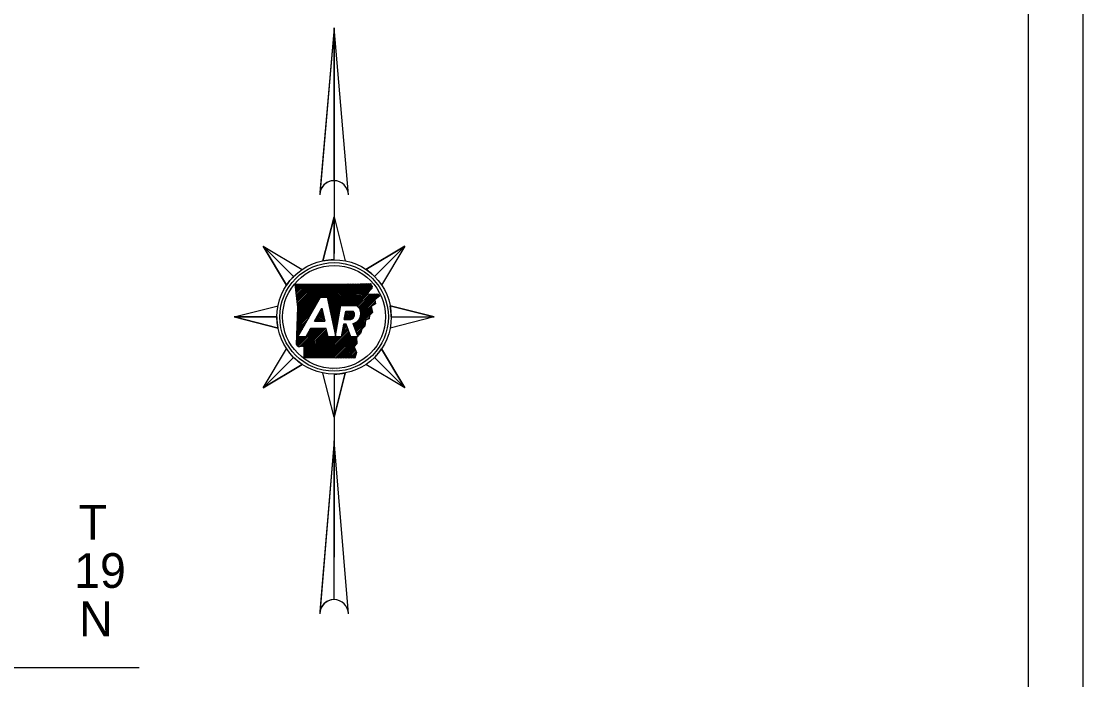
# Model space of a CAD drawing. Extents: x 19118 to 454486, y 1325406 to 1693506.
# Drawn here: x 26165 to 27093, y 1325966 to 1326542 of the extents above; entities that cross this region are included whole.
import ezdxf

# ---------------------------------------------------------------- set-up
doc = ezdxf.new("R2010")
doc.units = 0
for name, color, linetype in [('S_CURB', 7, 'Continuous'), ('S_EDGE_PAVEMENT', 7, 'Continuous'), ('S_MSC_PT_SYM', 7, 'Continuous'), ('S_SHOULDER', 7, 'Continuous')]:
    doc.layers.add(name, color=color, linetype=linetype)

msp = doc.modelspace()

# ---------------------------------------------------------------- linework, layer by layer
at = {"layer": 'S_CURB'}
for p, q in [((26438.45, 1326535.94), (26426.13, 1326391.81)), ((26438.45, 1326535.94), (26438.45, 1326338.55)), ((26438.45, 1326402.19), (26438.45, 1326535.94)), ((26426.37, 1326394.59), (26427.51, 1326395.73)), ((26426.3, 1326393.82), (26426.86, 1326394.38)), ((26438.45, 1326370.59), (26428.71, 1326332.13)), ((26438.45, 1326333.09), (26438.45, 1326370.59)), ((26376.58, 1326344.96), (26403.09, 1326318.44)), ((26403.09, 1326318.44), (26376.58, 1326344.96)), ((26376.58, 1326344.96), (26396.88, 1326310.88)), ((26500.32, 1326344.96), (26466.24, 1326324.65)), ((26473.8, 1326318.44), (26500.32, 1326344.96)), ((26473.8, 1326318.44), (26500.32, 1326344.96)), ((26406.87, 1326265.57), (26426.6, 1326300.41)), ((26426.6, 1326300.41), (26432.46, 1326300.41)), ((26444.36, 1326293.14), (26458.06, 1326293.14)), ((26421.38, 1326279.25), (26427.83, 1326290.64)), ((26448.63, 1326288.23), (26455.06, 1326288.23)), ((26525.95, 1326283.09), (26487.49, 1326292.82)), ((26350.95, 1326283.09), (26388.45, 1326283.09)), ((26388.45, 1326283.09), (26350.95, 1326283.09)), ((26350.95, 1326283.09), (26389.41, 1326273.35)), ((26421.38, 1326279.25), (26430.27, 1326279.25)), ((26448.99, 1326276.65), (26446.61, 1326276.65)), ((26447.33, 1326280.79), (26453.21, 1326280.79)), ((26453.08, 1326265.57), (26448.99, 1326276.65)), ((26454.79, 1326277.24), (26459.1, 1326265.57)), ((26488.45, 1326283.09), (26525.95, 1326283.09)), ((26488.45, 1326283.09), (26525.95, 1326283.09)), ((26413.64, 1326265.57), (26406.87, 1326265.57)), ((26417.78, 1326272.88), (26413.64, 1326265.57)), ((26431.64, 1326272.88), (26417.78, 1326272.88)), ((26444.68, 1326265.57), (26433.2, 1326265.57)), ((26459.1, 1326265.57), (26453.08, 1326265.57)), ((26376.58, 1326221.22), (26403.09, 1326247.73)), ((26403.09, 1326247.73), (26376.58, 1326221.22)), ((26473.8, 1326247.73), (26500.32, 1326221.22)), ((26473.8, 1326247.73), (26500.32, 1326221.22)), ((26500.32, 1326221.22), (26480.01, 1326255.29)), ((26376.58, 1326221.22), (26410.65, 1326241.52)), ((26438.44, 1326233.09), (26438.45, 1326233.09)), ((26438.45, 1326195.59), (26448.18, 1326234.04)), ((26438.45, 1326233.09), (26438.45, 1326073.03)), ((26438.45, 1326233.09), (26438.45, 1326195.59)), ((26438.45, 1326174.69), (26426.12, 1326025.49)), ((26438.45, 1326035.94), (26438.45, 1326174.69)), ((26142.72, 1325976.56), (26267.96, 1325976.56))]:
    msp.add_line(p, q, dxfattribs=at)
for points in [[(26450.95, 1326389.69), (26438.45, 1326535.94), (26425.95, 1326389.69)], [(26428.71, 1326332.13), (26438.45, 1326370.59), (26448.18, 1326332.13)], [(26396.88, 1326310.88), (26376.58, 1326344.96), (26410.65, 1326324.65)], [(26466.24, 1326324.65), (26500.32, 1326344.96), (26480.01, 1326310.88)], [(26404.31, 1326311.71), (26423.82, 1326311.7), (26440.94, 1326311.73), (26461.14, 1326312.05), (26470.51, 1326312.26)], [(26405.72, 1326258.92), (26406.81, 1326291.66), (26404.31, 1326311.71)], [(26476.63, 1326303.3), (26478.32, 1326301.54), (26474.11, 1326298.08), (26474.57, 1326294.58), (26470.96, 1326292.2), (26472.19, 1326286.83), (26469.41, 1326284.29), (26469.16, 1326281.53), (26465.78, 1326280.31), (26465.25, 1326275.11), (26462.82, 1326272.5), (26461.65, 1326268.58), (26458.1, 1326265.34), (26458.37, 1326259.62), (26455.97, 1326256.93), (26458.16, 1326252.02), (26456.64, 1326247.14)], [(26467.61, 1326302.84), (26476.77, 1326303.31)], [(26432.46, 1326300.41), (26439.72, 1326266.5), (26444.36, 1326293.14)], [(26389.41, 1326273.35), (26350.95, 1326283.09), (26389.41, 1326292.82)], [(26427.83, 1326290.64), (26430.27, 1326279.25)], [(26447.33, 1326280.79), (26448.63, 1326288.23)], [(26487.49, 1326292.82), (26525.95, 1326283.09), (26487.49, 1326273.35)], [(26446.61, 1326276.65), (26444.68, 1326265.57)], [(26433.2, 1326265.57), (26431.64, 1326272.88)], [(26456.64, 1326247.14), (26412.42, 1326247.22), (26412.4, 1326256.98)], [(26410.65, 1326241.52), (26376.58, 1326221.22), (26396.88, 1326255.29)], [(26480.01, 1326255.29), (26500.32, 1326221.22), (26466.24, 1326241.52)], [(26448.18, 1326234.04), (26438.45, 1326195.59), (26428.71, 1326234.04)], [(26450.95, 1326023.44), (26438.45, 1326174.69), (26425.95, 1326023.44)]]:
    msp.add_lwpolyline(points, dxfattribs=at)
for radius in [50, 45]:
    msp.add_circle((26438.45, 1326283.09), radius, dxfattribs=at)
for centre, radius, start, end in [((26438.45, 1326389.69), 12.5, 0, 180), ((26438.45, 1326389.69), 12.5, 90, 170.22959), ((26438.45, 1326283.09), 50, 90, 101.22909), ((26438.45, 1326283.09), 50, 45, 56.22909), ((26438.45, 1326283.09), 50, 135, 146.22909), ((26452.97, 1326285.91), 8.85, 281.86262, 54.87052), ((26451.8, 1326285.09), 4.53, 288.12683, 43.89016), ((26438.45, 1326283.09), 50, 0, 11.22909), ((26438.45, 1326283.09), 50, 180, 191.22909), ((26438.45, 1326283.09), 50, 225, 236.22909), ((26438.45, 1326283.09), 50, 315, 326.22909), ((26438.45, 1326283.09), 50, 270, 281.22909), ((26438.45, 1326023.44), 12.5, 0, 180), ((26438.45, 1326023.44), 12.5, 90, 170.5511)]:
    msp.add_arc(centre, radius, start, end, dxfattribs=at)
for points in [[(26470.51, 1326312.26), (26470.57, 1326311.73), (26470.73, 1326311.46), (26470.76, 1326310.95), (26470.96, 1326310.73), (26471.31, 1326310.51), (26471.63, 1326310.16), (26471.7, 1326309.75), (26471.6, 1326309.33), (26471.58, 1326308.86), (26471.53, 1326308.45), (26471.46, 1326308.08), (26471.17, 1326307.78), (26470.89, 1326307.56), (26470.64, 1326307.31), (26470.46, 1326307.04), (26470.14, 1326306.75), (26469.83, 1326306.45), (26469.58, 1326306.18), (26469.32, 1326305.85), (26469.2, 1326305.47), (26468.92, 1326305.21), (26468.71, 1326304.96), (26468.42, 1326304.64), (26468.27, 1326304.31), (26468, 1326303.94), (26467.94, 1326303.58), (26467.75, 1326303.29), (26467.74, 1326303.24)], [(26412.4, 1326256.98), (26412.44, 1326256.95), (26412.21, 1326257.11), (26411.9, 1326257.27), (26411.55, 1326257.29), (26411.1, 1326257.35), (26410.73, 1326257.39), (26410.34, 1326257.64), (26409.93, 1326257.38), (26409.48, 1326257.18), (26409.21, 1326257.4), (26408.86, 1326257.26), (26408.62, 1326257.33), (26408.2, 1326257.04), (26407.8, 1326257.15), (26407.51, 1326257.06), (26407.15, 1326257.07), (26407.07, 1326257.49), (26406.72, 1326257.55), (26406.42, 1326257.71), (26406.22, 1326258.14), (26406.07, 1326258.46), (26405.72, 1326258.92)]]:
    msp.add_spline(points, degree=3, dxfattribs=at)
at = {"layer": 'S_EDGE_PAVEMENT'}
msp.add_lwpolyline([(23759.74, 1327539.29), (27093.14, 1327539.29), (27093.14, 1325405.92), (23759.74, 1325405.92)], close=True, dxfattribs=at)
at = {"layer": 'S_MSC_PT_SYM'}
for p, q in [((26404.37, 1326311.27), (26404.81, 1326311.71)), ((26404.52, 1326310.01), (26406.22, 1326311.71)), ((26404.68, 1326308.75), (26407.63, 1326311.71)), ((26404.84, 1326307.5), (26409.05, 1326311.71)), ((26404.99, 1326306.24), (26410.46, 1326311.71)), ((26405.15, 1326304.98), (26411.87, 1326311.7)), ((26405.31, 1326303.72), (26413.29, 1326311.7)), ((26405.46, 1326302.46), (26414.7, 1326311.7)), ((26405.62, 1326301.21), (26416.11, 1326311.7)), ((26405.78, 1326299.95), (26417.53, 1326311.7)), ((26405.93, 1326298.69), (26418.94, 1326311.7)), ((26406.09, 1326297.43), (26420.35, 1326311.7)), ((26406.25, 1326296.18), (26421.77, 1326311.7)), ((26406.4, 1326294.92), (26423.18, 1326311.7)), ((26406.45, 1326280.82), (26437.35, 1326311.73)), ((26406.5, 1326282.29), (26435.93, 1326311.72)), ((26406.55, 1326283.75), (26434.52, 1326311.72)), ((26406.56, 1326293.66), (26424.6, 1326311.7)), ((26406.6, 1326285.21), (26433.1, 1326311.72)), ((26406.64, 1326286.68), (26431.68, 1326311.71)), ((26406.69, 1326288.14), (26430.27, 1326311.71)), ((26406.72, 1326292.4), (26426.01, 1326311.7)), ((26406.74, 1326289.6), (26428.85, 1326311.71)), ((26406.79, 1326291.06), (26427.43, 1326311.7)), ((26427.45, 1326300.41), (26438.77, 1326311.73)), ((26428.87, 1326300.41), (26440.19, 1326311.73)), ((26430.28, 1326300.41), (26441.61, 1326311.74)), ((26431.69, 1326300.41), (26443.05, 1326311.77)), ((26432.57, 1326299.88), (26444.48, 1326311.79)), ((26432.82, 1326298.71), (26445.92, 1326311.81)), ((26433.07, 1326297.55), (26447.36, 1326311.83)), ((26433.32, 1326296.38), (26448.79, 1326311.86)), ((26433.57, 1326295.22), (26450.23, 1326311.88)), ((26433.82, 1326294.05), (26451.67, 1326311.9)), ((26434.07, 1326292.89), (26453.1, 1326311.92)), ((26434.32, 1326291.72), (26454.54, 1326311.94)), ((26434.57, 1326290.56), (26455.98, 1326311.97)), ((26434.82, 1326289.39), (26457.41, 1326311.99)), ((26435.07, 1326288.23), (26458.85, 1326312.01)), ((26435.32, 1326287.06), (26460.29, 1326312.03)), ((26435.57, 1326285.9), (26461.73, 1326312.06)), ((26435.82, 1326284.73), (26463.18, 1326312.09)), ((26445.64, 1326293.14), (26464.62, 1326312.13)), ((26447.05, 1326293.14), (26466.07, 1326312.16)), ((26448.47, 1326293.14), (26467.52, 1326312.2)), ((26449.88, 1326293.14), (26468.97, 1326312.23)), ((26451.3, 1326293.14), (26470.41, 1326312.26)), ((26452.71, 1326293.14), (26470.73, 1326311.16)), ((26454.12, 1326293.14), (26471.41, 1326310.43)), ((26455.54, 1326293.14), (26471.6, 1326309.2)), ((26456.95, 1326293.14), (26468.37, 1326304.56)), ((26458.24, 1326293.01), (26468.09, 1326302.87)), ((26459.01, 1326292.37), (26469.58, 1326302.94)), ((26459.7, 1326291.65), (26471.07, 1326303.02)), ((26460.31, 1326290.84), (26472.56, 1326303.1)), ((26460.84, 1326289.96), (26474.05, 1326303.17)), ((26461.27, 1326288.97), (26475.54, 1326303.25)), ((26461.59, 1326287.88), (26476.89, 1326303.18)), ((26461.78, 1326286.66), (26477.55, 1326302.42)), ((26406.35, 1326277.9), (26423.64, 1326295.18)), ((26406.4, 1326279.36), (26425.48, 1326298.44)), ((26461.5, 1326283.55), (26474.33, 1326296.38)), ((26461.79, 1326285.26), (26474.17, 1326297.63)), ((26472.75, 1326293.38), (26474.5, 1326295.13)), ((26476.92, 1326300.38), (26478.21, 1326301.67)), ((26406.21, 1326273.51), (26418.1, 1326285.4)), ((26406.26, 1326274.97), (26419.95, 1326288.66)), ((26406.3, 1326276.44), (26421.79, 1326291.92)), ((26421.45, 1326279.25), (26428.72, 1326286.51)), ((26422.87, 1326279.25), (26428.97, 1326285.35)), ((26423.14, 1326282.35), (26428.47, 1326287.68)), ((26424.28, 1326279.25), (26429.22, 1326284.18)), ((26424.99, 1326285.61), (26428.22, 1326288.84)), ((26426.83, 1326288.87), (26427.97, 1326290.01)), ((26436.06, 1326283.57), (26444.09, 1326291.59)), ((26436.31, 1326282.4), (26443.79, 1326289.88)), ((26436.56, 1326281.24), (26443.49, 1326288.17)), ((26436.81, 1326280.07), (26443.19, 1326286.46)), ((26437.06, 1326278.91), (26442.9, 1326284.74)), ((26447.34, 1326280.79), (26454.78, 1326288.23)), ((26447.63, 1326282.49), (26453.37, 1326288.23)), ((26447.93, 1326284.2), (26451.95, 1326288.23)), ((26448.23, 1326285.91), (26450.54, 1326288.23)), ((26448.53, 1326287.63), (26449.12, 1326288.23)), ((26448.76, 1326280.79), (26455.57, 1326287.6)), ((26450.17, 1326280.79), (26456.04, 1326286.66)), ((26451.58, 1326280.79), (26456.31, 1326285.51)), ((26453, 1326280.79), (26456.19, 1326283.98)), ((26455.66, 1326274.88), (26471.34, 1326290.56)), ((26456.04, 1326273.85), (26471.6, 1326289.41)), ((26456.42, 1326272.81), (26471.87, 1326288.26)), ((26456.8, 1326271.78), (26472.13, 1326287.11)), ((26460.27, 1326280.9), (26471.07, 1326291.71)), ((26406.06, 1326269.12), (26412.56, 1326275.62)), ((26406.11, 1326270.59), (26414.41, 1326278.88)), ((26406.16, 1326272.05), (26416.25, 1326282.14)), ((26425.69, 1326279.25), (26429.47, 1326283.02)), ((26427.11, 1326279.25), (26429.72, 1326281.85)), ((26428.52, 1326279.25), (26429.96, 1326280.69)), ((26429.94, 1326279.25), (26430.21, 1326279.52)), ((26437.31, 1326277.74), (26442.6, 1326283.03)), ((26437.56, 1326276.58), (26442.3, 1326281.32)), ((26437.81, 1326275.41), (26442, 1326279.61)), ((26438.06, 1326274.25), (26441.7, 1326277.89)), ((26438.31, 1326273.08), (26441.4, 1326276.18)), ((26445.52, 1326270.4), (26449.74, 1326274.62)), ((26445.82, 1326272.11), (26449.36, 1326275.65)), ((26446.12, 1326273.83), (26448.95, 1326276.65)), ((26446.42, 1326275.54), (26447.53, 1326276.65)), ((26454.9, 1326276.94), (26455.33, 1326277.37)), ((26455.28, 1326275.91), (26457.97, 1326278.6)), ((26457.19, 1326270.75), (26465.67, 1326279.23)), ((26457.57, 1326269.72), (26465.51, 1326277.66)), ((26457.95, 1326268.68), (26465.35, 1326276.09)), ((26467.3, 1326280.86), (26469.28, 1326282.84)), ((26405.74, 1326258.91), (26412.41, 1326265.57)), ((26405.77, 1326260.35), (26411, 1326265.57)), ((26405.82, 1326261.81), (26409.58, 1326265.57)), ((26405.87, 1326263.27), (26408.17, 1326265.57)), ((26405.92, 1326264.73), (26407.02, 1326265.84)), ((26405.96, 1326266.2), (26408.87, 1326269.1)), ((26406.01, 1326267.66), (26410.72, 1326272.36)), ((26406.27, 1326258.02), (26421.13, 1326272.88)), ((26407.11, 1326257.44), (26422.55, 1326272.88)), ((26408.13, 1326257.05), (26423.96, 1326272.88)), ((26409.81, 1326257.31), (26425.38, 1326272.88)), ((26411.24, 1326257.33), (26426.79, 1326272.88)), ((26412.35, 1326257.03), (26428.21, 1326272.88)), ((26412.4, 1326254.25), (26431.03, 1326272.88)), ((26412.4, 1326255.66), (26429.62, 1326272.88)), ((26412.41, 1326252.84), (26431.78, 1326272.21)), ((26412.41, 1326251.43), (26432.03, 1326271.05)), ((26412.41, 1326250.02), (26432.28, 1326269.88)), ((26412.42, 1326248.61), (26432.53, 1326268.72)), ((26412.44, 1326247.22), (26432.78, 1326267.55)), ((26413.85, 1326247.21), (26433.03, 1326266.39)), ((26415.24, 1326268.4), (26419.72, 1326272.88)), ((26415.26, 1326247.21), (26433.62, 1326265.57)), ((26416.68, 1326247.21), (26435.04, 1326265.57)), ((26417.09, 1326271.66), (26418.31, 1326272.88)), ((26418.09, 1326247.21), (26436.45, 1326265.57)), ((26419.5, 1326247.21), (26437.87, 1326265.57)), ((26420.91, 1326247.2), (26439.28, 1326265.57)), ((26422.32, 1326247.2), (26440.69, 1326265.57)), ((26423.74, 1326247.2), (26442.11, 1326265.57)), ((26425.15, 1326247.2), (26443.52, 1326265.57)), ((26426.56, 1326247.19), (26450.88, 1326271.52)), ((26427.97, 1326247.19), (26451.26, 1326270.49)), ((26429.38, 1326247.19), (26451.65, 1326269.45)), ((26430.8, 1326247.19), (26452.03, 1326268.42)), ((26432.21, 1326247.18), (26452.41, 1326267.39)), ((26433.62, 1326247.18), (26452.79, 1326266.35)), ((26435.03, 1326247.18), (26453.42, 1326265.57)), ((26436.44, 1326247.18), (26454.84, 1326265.57)), ((26437.85, 1326247.18), (26456.25, 1326265.57)), ((26438.56, 1326271.92), (26441.1, 1326274.47)), ((26438.81, 1326270.75), (26440.81, 1326272.75)), ((26439.06, 1326269.59), (26440.51, 1326271.04)), ((26439.27, 1326247.17), (26457.66, 1326265.57)), ((26439.31, 1326268.43), (26440.21, 1326269.33)), ((26439.55, 1326267.26), (26439.91, 1326267.62)), ((26444.93, 1326266.97), (26450.5, 1326272.55)), ((26445.22, 1326268.69), (26450.12, 1326273.58)), ((26458.33, 1326267.65), (26462.67, 1326271.99)), ((26458.71, 1326266.62), (26462.06, 1326269.97)), ((26440.68, 1326247.17), (26458.14, 1326264.63)), ((26442.09, 1326247.17), (26458.2, 1326263.28)), ((26443.5, 1326247.17), (26458.27, 1326261.93)), ((26444.91, 1326247.16), (26458.33, 1326260.58)), ((26446.33, 1326247.16), (26456.01, 1326256.84)), ((26447.74, 1326247.16), (26456.44, 1326255.86)), ((26449.15, 1326247.16), (26456.88, 1326254.89)), ((26450.56, 1326247.15), (26457.32, 1326253.91)), ((26451.97, 1326247.15), (26457.75, 1326252.93)), ((26453.39, 1326247.15), (26458.12, 1326251.88)), ((26454.8, 1326247.15), (26457.48, 1326249.83)), ((26456.21, 1326247.15), (26456.84, 1326247.77))]:
    msp.add_line(p, q, dxfattribs=at)
msp.add_circle((26438.45, 1326283.09), 47.5, dxfattribs=at)
at = {"layer": 'S_SHOULDER'}
msp.add_line((27045.61, 1325445.75), (27045.61, 1327500.35), dxfattribs=at)

# ---------------------------------------------------------------- texts
at = {"layer": 'S_CURB'}
for s, height, p in [('DWB 7-27-17', 0.9722, (26435.39, 1326237.25)), ('T', 30.36, (26215.01, 1326088.4)), ('19', 30.36, (26211.19, 1326046.18)), ('N', 30.36, (26215.49, 1326003.96))]:
    msp.add_text(s, height=height, dxfattribs=at).set_placement(p)

doc.saveas('drawing.dxf')
